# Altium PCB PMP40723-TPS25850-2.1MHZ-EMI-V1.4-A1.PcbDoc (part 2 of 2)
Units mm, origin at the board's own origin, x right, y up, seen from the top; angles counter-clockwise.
Board outline 50 x 35 mm, 4 copper layers (Top Layer, Signal Layer 1, Signal Layer 2, Bottom Layer), stack 1.647 mm thick; 79 components, 26 nets, 228 pads, 232 vias.
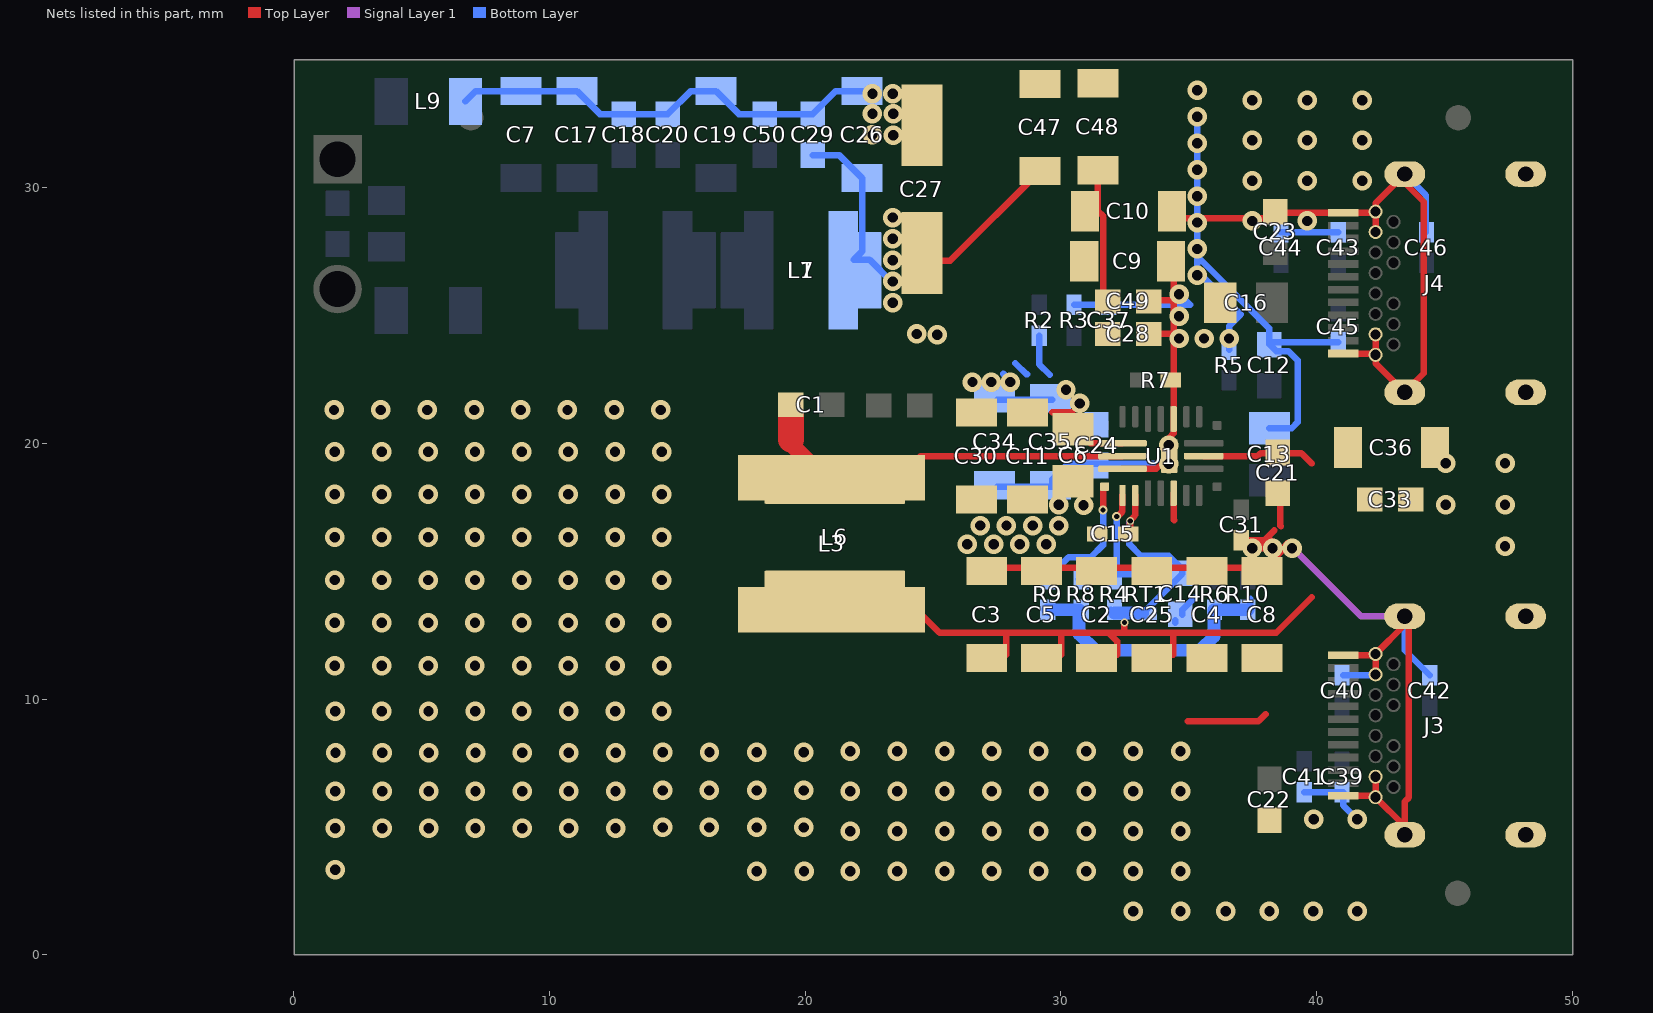
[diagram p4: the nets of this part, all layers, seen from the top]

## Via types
v1: diameter 0.762, hole 0.406, Top Layer to Bottom Layer, 201 vias
v2: diameter 0.305, hole 0.203, Top Layer to Bottom Layer, 11 vias
v3: diameter 0.356, hole 0.203, Top Layer to Bottom Layer, 8 vias
v4: diameter 0.762, hole 0.406, Top Layer to Bottom Layer, tented top, 8 vias
v5: diameter 0.356, hole 0.203, Top Layer to Bottom Layer, tented top, 2 vias
v6: diameter 0.305, hole 0.203, Top Layer to Bottom Layer, tented top, 2 vias

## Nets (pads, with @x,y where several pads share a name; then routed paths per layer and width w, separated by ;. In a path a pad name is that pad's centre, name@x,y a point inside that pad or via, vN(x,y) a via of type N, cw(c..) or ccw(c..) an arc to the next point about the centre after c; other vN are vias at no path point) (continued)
PGND: C2.2 C3.2 C4.2 C5.2 C6.2 C7.2 C8.2 C9.2 C10.2 C11.2 C12.2 C13.2 C14.2 C15.2 C16.2 C17.2 C18.2 C19.2 C20.2 C21.2 C22.2 C23.2 C24.2 C25.2 C26.2 C27.2 C28.2 C29.2 C30.2 C31.2 C33.2 C34.2 C35.2 C36.2 C37.2 C39.2 C40.2 C41.2 C42.2 C43.2 C44.2 C45.2 C46.2 C47.2 C48.2 C49.2 C50.2 J3.A1 J3.A12 J3.B1 J3.B12 J3.M1 J3.M2 J3.S1 J3.S2 J3.S3 J3.S4 J4.A1 J4.A12 J4.B1 J4.B12 J4.M1 J4.M2 J4.S1 J4.S2 J4.S3 J4.S4 L9.2 R3.1 R5.1 R6.1 R7.1 R8.1 R9.1 R10.1 U1.6 U1.16 U1.24 U1.25 | length 155.2
  Top Layer w0.254: C3.2@27.783,15.137 30.078,15.137 ; 30.072,15.143 30.078,15.137 ; C6.2@30.881,18.146 C6.2@31.124,18.39 ; U1.24@32.404,19.007 33.729,19.007 U1.25@34.229,19.507 ; C28.2@33.434,24.283 34.328,24.283 v1@34.404,24.206 ; C49.2@33.434,25.603 34.303,25.603 34.404,25.502 ; v1@34.236,20.227 34.404,20.395 U1.16@34.404,20.957 34.411,20.964 34.411,22.548 34.407,22.544 34.407,22.393 R7.1@34.404,22.39 ; C9.2@34.244,27.567 34.204,27.567 C9.2@34.259,27.621 ; R7.1@34.361,22.347 R7.1@34.404,22.39 ; U1.6@34.404,18.057 34.404,17.025 34.437,16.993 ; C10.2@34.619,28.817 38.004,28.817 38.204,29.017 J4.A12@41.044,29.017 42.254,29.017 J4.B1@42.304,29.067 ; C9.2@34.716,27.432 34.404,27.12 34.404,25.502 ; 34.963,9.133 37.72,9.133 38.004,9.417 ; C31.2@37.054,16.215 37.956,16.215 ; v1(37.486,15.901) v1@37.641,15.901 ; 38.349,16.609 37.956,16.215 ; C21.2@38.578,18.098 38.578,16.79 38.604,16.764 ; J3.A1@41.044,6.217 42.254,6.217 J3.B12@42.304,6.167 ; J3.A12@41.044,11.717 42.254,11.717 J3.B1@42.304,11.767 ; J4.A1@41.044,23.517 J4.B12@42.254,23.517 ; J3.M2@42.304,6.967 J3.B12@42.304,6.167 ; J3.M1@42.304,10.967 J3.B1@42.304,11.767 ; J4.M2@42.304,24.267 42.304,23.567 J4.B12@42.254,23.517 ; J4.M1@42.304,28.267 J4.B1@42.304,29.067 ; J3.S1@43.444,4.697 J3.S1@43.444,5.027 ; 30.078,15.137 37.977,15.137 38.909,16.068 38.873,16.104 38.67,15.901 v1(38.273,15.901) 37.888,15.901 ; R7.1@34.404,22.39 34.404,23.622 v1@34.404,24.206 ; v1@34.404,24.206 34.404,25.502 ; v1@37.641,15.901 37.888,15.901 ; v1@37.641,15.901 37.956,16.215 ; 37.888,15.901 38.203,16.215 37.956,16.215 ; J4.B12@42.254,23.517 J4.B12@42.304,23.467 42.304,23.137 J4.S1@43.444,21.997 44.19,22.743 44.19,29.449 43.444,30.195 J4.S4@43.444,30.537 42.304,29.397 J4.B1@42.304,29.067 ; J3.B12@42.304,6.167 J3.S1@43.444,5.027 ; J3.B1@42.304,11.767 43.444,12.907 J3.S4@43.444,13.237 43.606,13.075 43.606,6.155 43.444,5.993 J3.S1@43.444,5.027
  Signal Layer 1 w0.254: v1@38.928,16.05 41.742,13.237 J3.S4@43.444,13.237
  Bottom Layer w0.254: L9.2@6.706,33.376 7.11,33.78 C7.2@8.885,33.78 C17.2@11.07,33.78 11.97,32.88 C18.2@12.898,32.88 C20.2@14.626,32.88 15.526,33.78 C19.2@16.505,33.78 17.405,32.88 C50.2@18.41,32.88 C29.2@20.29,32.88 21.19,33.78 C26.2@22.22,33.78 ; C34.2@27.503,18.315 29.662,18.315 29.662,18.593 30.285,19.215 34.196,19.215 v1(34.209,19.203) ; R3.1@30.51,25.416 C37.2@31.866,25.416 35.051,25.416 34.635,25.832 v1(34.615,25.832) ; C14.2@34.463,12.992 C14.2@34.463,13.092 ; C14.2@34.742,13.297 34.742,13.488 35.225,13.97 ; v1@35.327,32.995 35.327,28.564 v1@35.327,27.317 ; R5.1@36.571,23.663 v1(36.571,24.105) 36.571,24.587 37.028,25.045 35.327,26.746 v1@35.327,27.317 ; R10.1@37.409,13.497 37.409,13.919 ; C13.2@38.147,20.6 39.023,20.6 39.252,20.828 39.252,23.253 38.892,23.612 38.422,23.612 C12.2@38.146,23.889 ; C44.2@38.603,28.261 39.645,28.261 ; C41.2@39.518,6.367 41.042,6.367 41.042,5.842 v1(41.584,5.3) ; v4(39.626,28.702) 39.626,28.28 39.645,28.261 ; C45.2@40.838,23.962 38.219,23.962 C12.2@38.146,23.889 ; C43.2@40.838,28.261 39.645,28.261 ; C40.2@41.042,10.938 42.276,10.938 J3.M1@42.304,10.967 ; J3.S4@43.444,13.237 43.444,11.914 C42.2@44.42,10.938 ; J4.S4@43.444,30.537 44.267,29.713 C46.2@44.267,28.261 ; v1@35.327,27.317 38.146,24.498 C12.2@38.146,23.889
  Bottom Layer w0.508: R9.1@29.485,13.497 30.704,13.497 30.704,12.548 31.339,11.913 35.45,11.913 35.987,12.449 35.987,13.48 R6.1@36.004,13.497 R10.1@37.308,13.497
  other v1: 32.828,1.707 34.674,1.702 36.439,1.702 38.154,1.702 39.869,1.702 41.584,1.702 18.105,3.277 19.951,3.277 21.754,3.267 23.6,3.267 25.446,3.267 27.291,3.267 29.137,3.267 30.983,3.267 32.828,3.267 34.674,3.267 1.624,3.328 21.754,4.831 23.6,4.831 25.446,4.831 27.291,4.831 29.137,4.831 30.983,4.831 32.828,4.831 34.674,4.831 1.624,4.953 3.45,4.953 5.275,4.953 7.101,4.953 8.926,4.953 10.752,4.953 12.578,4.953 14.424,4.982 16.25,4.982 18.096,4.982 19.941,4.982 39.883,5.3 1.624,6.401 3.45,6.401 5.275,6.401 7.101,6.401 8.926,6.401 10.752,6.401 12.578,6.401 21.754,6.396 23.6,6.396 25.446,6.396 27.291,6.396 29.137,6.396 30.983,6.396 32.828,6.396 34.674,6.396 14.424,6.429 16.25,6.429 18.096,6.429 19.941,6.429 1.627,7.9 3.453,7.9 5.278,7.9 7.104,7.9 8.93,7.9 10.755,7.9 12.581,7.9 14.428,7.928 16.253,7.928 18.099,7.928 19.945,7.928 21.754,7.961 23.6,7.961 25.446,7.961 27.291,7.961 29.137,7.961 30.983,7.961 32.828,7.961 34.674,7.961 1.612,9.525 3.438,9.525 5.264,9.525 7.089,9.525 8.915,9.525 10.741,9.525 12.566,9.525 14.392,9.525 1.605,11.31 3.43,11.31 5.256,11.31 7.082,11.31 8.907,11.31 10.733,11.31 12.558,11.31 14.384,11.31 1.605,12.985 3.43,12.985 5.256,12.985 7.082,12.985 8.907,12.985 10.733,12.985 12.558,12.985 14.384,12.985 1.605,14.659 3.43,14.659 5.256,14.659 7.082,14.659 8.907,14.659 10.733,14.659 12.558,14.659 14.384,14.659 39.035,15.901 47.366,15.985 26.335,16.053 27.364,16.053 28.392,16.053 29.421,16.053 1.605,16.334 3.43,16.334 5.256,16.334 7.082,16.334 8.907,16.334 10.733,16.334 12.558,16.334 14.384,16.334 26.843,16.79 27.867,16.79 28.892,16.79 29.916,16.79 30.882,17.577 29.916,17.602 45.042,17.602 47.366,17.602 1.605,18.009 3.43,18.009 5.256,18.009 7.082,18.009 8.907,18.009 10.733,18.009 12.558,18.009 14.384,18.009 45.042,19.22 47.366,19.22 1.605,19.683 3.43,19.683 5.256,19.683 7.082,19.683 8.907,19.683 10.733,19.683 12.558,19.683 14.384,19.683 34.209,19.939 1.57,21.311 3.396,21.311 5.221,21.311 7.047,21.311 8.872,21.311 10.698,21.311 12.524,21.311 14.349,21.311 34.615,24.105 35.593,24.105 25.167,24.257 24.354,24.283 34.615,24.968 35.327,26.572 35.327,27.606 35.327,28.639 35.327,29.673 41.778,30.277 35.327,30.707 35.327,31.74 41.778,31.852 23.439,32.055 22.627,32.08 35.327,32.774 22.627,32.893 23.439,32.893 41.778,33.427 22.627,33.681 23.414,33.681 35.327,33.808
  other v4: 37.473,28.702 37.473,30.277 39.626,30.277 37.473,31.852 39.626,31.852 37.473,33.427 39.626,33.427
SENS: C2.1 C3.1 C4.1 C5.1 C8.1 C14.1 C15.1 C21.1 C25.1 C33.1 C36.1 L3.2 L6.2 R4.2 RT1.2 U1.3 U1.11 | length 35
  Top Layer w0.254: L3.2@23.846,14.006 25.252,12.6 27.834,12.6 ; C3.1@27.859,11.737 27.859,12.575 27.834,12.6 ; C5.1@30.003,11.737 30.003,12.531 30.072,12.6 ; 32.198,11.737 32.198,12.255 31.857,12.596 ; v2(32.482,12.996) 32.482,12.6 ; C15.1@32.625,16.459 C15.1@32.685,16.52 ; v2@32.685,16.967 C15.1@32.685,16.52 ; v2@32.696,16.982 32.861,17.148 32.861,17.16 32.904,17.202 U1.3@32.904,17.97 ; v2(32.71,16.967) 32.71,16.545 C15.1@32.685,16.52 ; 34.393,11.737 34.393,12.583 34.411,12.6 ; U1.11@35.579,19.507 37.695,19.507 37.804,19.617 39.404,19.617 39.804,19.216 ; 39.804,13.986 38.419,12.6 34.411,12.6 ; 27.834,12.6 30.072,12.6 ; 30.072,12.6 31.567,12.6 31.572,12.596 31.857,12.596 ; 31.857,12.596 32.198,12.596 32.202,12.6 32.482,12.6 ; 32.482,12.6 34.411,12.6
  Bottom Layer w0.254: R4.2@31.948,13.497 R4.2@32.085,13.361 ; v2(32.482,12.996) 32.482,13.361 ; v2@32.668,16.918 32.668,16.064 33.121,15.611 34.218,15.611 34.742,15.086 34.742,14.897 33.312,13.466 RT1.2@33.312,13.335 ; v2@32.71,16.918 v2(32.71,16.967)
  Bottom Layer w0.508: R4.2@32.085,13.361 32.482,13.361 RT1.2@33.193,13.361
SW: C1.1 L3.1 L6.1 U1.23 | length 13.6
  Top Layer w0.254: L3.1@20.828,19.344 L3.1@21.636,19.344 ; L3.1@24.176,19.166 24.517,19.507 U1.23@32.404,19.507
  Top Layer w0.5: L3.1@22.13,19.217 L3.1@22.692,19.217
  Top Layer w0.635: 19.439,20.155 19.35,20.066 20.55,18.866 L3.1@21.611,18.866
  Top Layer w1.016: 19.439,20.155 C1.1@19.439,21.162
TS: R4.1 R8.2 RT1.1 U1.2 | length 5.8
  Top Layer w0.254: v3(32.177,17.145) 32.212,17.145 32.228,17.161 32.228,17.167 32.404,17.344 U1.2@32.404,17.97
  Bottom Layer w0.254: R8.2@30.704,14.697 31.948,14.697 R4.1@32.136,14.885 ; v3(32.177,17.145) 32.177,14.925 R4.1@32.136,14.885 ; RT1.1@33.193,14.885 R4.1@32.136,14.885
VIN: C6.1 C9.1 C10.1 C11.1 C24.1 C26.1 C27.1 C28.1 C29.1 C30.1 C34.1 C35.1 C47.1 C48.1 C49.1 L1.2 L7.2 R2.2 U1.22 | length 27.3
  Top Layer w0.254: v1@23.389,27.151 25.671,27.151 C47.1@29.18,30.66 ; 29.654,21.217 30.441,21.217 ; C6.1@30.856,20.307 31.156,20.007 U1.22@32.404,20.007 ; C48.1@31.44,30.685 31.44,29.106 31.644,28.903 31.644,25.794 C49.1@31.834,25.603
  Bottom Layer w0.254: C29.1@20.29,31.28 21.32,31.28 C26.1@22.22,30.38 22.22,27.508 21.903,27.191 22.507,27.191 v1@23.389,26.309 ; C34.1@27.503,21.715 C35.1@29.662,21.715 ; 27.732,22.733 28.011,22.454 v1@28.011,22.428 ; 28.215,23.14 28.646,22.708 28.672,22.708 ; R2.2@29.154,24.216 29.154,23.089 29.561,22.682
  other v1: 30.729,21.565 30.196,22.098 26.538,22.403 27.275,22.403 28.011,22.403 23.414,25.502 23.414,26.335 23.414,27.169 23.414,28.002 23.414,28.835
VSET: R9.2 U1.1 | length 5
  Top Layer w0.254: v3(31.644,17.399) 31.644,18.247 U1.1@31.704,18.307
  Bottom Layer w0.254: R9.2@29.485,14.697 29.485,14.732 30.297,15.545 31.161,15.545 31.644,16.028 v3(31.644,17.399)
pads on no net: FID1.1 FID2.1 FID3.1 J3.A2 J3.A3 J3.A8 J3.A10 J3.A11 J3.B2 J3.B3 J3.B8 J3.B10 J3.B11 J4.A2 J4.A3 J4.A8 J4.A10 J4.A11 J4.B2 J4.B3 J4.B8 J4.B10 J4.B11

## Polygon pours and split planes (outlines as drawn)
VIN on Top Layer "TOP_LAYER_VIN_P134" (solid, remove dead copper, pour order 134): 22.855,29.312 24.938,29.312 27.3,31.674 32.2,31.674 32.456,31.418 32.456,30.277 32.456,26.137 32.456,23.47 31.898,22.911 30.805,22.911 30.551,22.657 30.551,22.352 31.288,21.616 31.288,20.139 31.156,20.007 31.072,20.092 30.043,20.092 29.51,20.625 25.903,20.625 25.779,20.749 25.779,22.965 25.929,23.114 28.144,23.114 30.183,25.153 30.183,26.387 30.183,29.401 29.815,29.769 28.392,29.769 25.573,26.95 25.573,25.248 25.319,24.994 22.787,24.994 22.41,25.371 22.41,28.965
SW on Top Layer "TOP_LAYER_SW_P120" (solid, remove dead copper, pour order 120): 17.19,20.015 17.496,20.32 18.602,20.32 18.932,20.65 19.835,20.65 20.166,20.32 29.383,20.32 29.535,20.168 29.535,19.736 29.612,19.66 29.612,19.406 29.535,19.33 29.535,18.695 29.442,18.602 25.688,18.602 25.586,18.499 25.586,17.702 25.384,17.501 17.336,17.501 17.19,17.647
no net on Top Layer "TOP_LAYER_NONET_P114" (solid, remove dead copper, pour order 114): 17.928,20.32
PGND on Top Layer "TOP_LAYER_PGND_P096" (solid, remove dead copper, pour order 96): 22.627,34.57 48.382,34.57 49.424,33.528 49.424,1.651 48.408,0.635 0.851,0.635 0.554,0.933 0.554,22.759 1.799,24.003 21.23,24.003 22.211,24.984 22.234,34.177
PB_BUS on Top Layer "TOP_LAYER_PB_BUS_P090" (solid, remove dead copper, pour order 90): 36.451,20.87 36.536,20.955 36.609,20.955 37.587,21.932 37.587,27.858 37.77,28.042 40.026,28.042 40.441,27.626 40.441,27.365 40.178,27.102 39.314,27.102 39.137,26.924 39.137,25.908 39.924,25.121 40.356,25.121 40.441,25.035 40.441,24.892 40.407,24.892 39.846,24.331 39.846,21.258 39.543,20.955 37.662,20.955 36.68,20.168 36.494,20.168 36.451,20.2
no net on Top Layer "TOP_LAYER_NONET_P088" (solid, remove dead copper, pour order 88): 36.104,20.523
SENS on Top Layer "TOP_LAYER_SENS_P086" (solid, remove dead copper, pour order 86): 36.399,19.513 37.689,20.803 42.159,20.803 42.896,20.066 42.896,14.443 38.755,10.236 17.597,10.236 17.19,10.644 17.19,15.161 17.625,15.596 25.376,15.596 25.573,15.399 25.573,13.44 25.779,13.234 38.786,13.234 40.711,15.159 40.711,18.568 40.234,19.045 37.669,19.045 37.384,19.33 36.583,19.33
no net on Top Layer "TOP_LAYER_NONET_P050" (solid, remove dead copper, pour order 50): 22.652,33.808
PA_BUS on Top Layer "TOP_LAYER_PA_BUS_P012" (solid, remove dead copper, pour order 12): 35.606,7.826 35.908,8.128 38.519,8.128 38.713,8.321 38.713,9.671 39.491,10.45 40.355,10.45 40.558,10.247 40.558,10.167 40.279,9.891 40.279,9.637 40.202,9.561 39.517,9.561 39.263,9.307 39.263,8.062 39.466,7.859 40.431,7.859 40.533,7.758 40.507,7.732 40.507,7.605 40.267,7.365 40.267,6.64 39.962,6.335 35.697,6.335 35.606,6.426
PA_BUS on Top Layer "TOP_LAYER_PA_BUS_P006" (solid, remove dead copper, pour order 6): 36.292,19.076 36.343,19.126 37.303,19.126 37.486,18.943 37.486,17.069 37.308,16.891 36.8,16.891 36.648,17.043 36.648,18.64 36.314,18.974 36.241,18.974
VIN on Signal Layer 1 "SIGNAL_LAYER_1_VIN_P098" (solid, remove dead copper, pour order 98): 26.157,22.733 26.53,23.106 29.705,23.106 29.761,23.114 31.216,21.66 31.207,21.052 30.788,20.633 27.698,20.633 26.157,22.174
PGND on Signal Layer 1 "SIGNAL_LAYER_1_PGND_P080" (solid, remove dead copper, pour order 80): 24.836,34.646 48.865,34.646 49.576,33.935 49.576,1.524 48.763,0.711 0.986,0.711 0.656,1.042 0.656,21.895 1.087,22.327 23.363,22.327 24.009,22.972 24.036,33.846
PA_BUS on Signal Layer 1 "SIGNAL_LAYER_1_PA_BUS_P044" (solid, remove dead copper, pour order 44): 36.725,19.164 37.36,19.164 37.487,19.037 37.487,17.005 37.36,16.878 36.725,16.878 36.598,17.005 36.598,19.037
PGND on Signal Layer 2 "SIGNAL_LAYER_2_PGND_P112" (solid, remove dead copper, pour order 112): 24.278,34.57 48.665,34.57 49.554,33.681 49.554,1.27 48.919,0.635 1.007,0.635 0.634,1.009 0.634,21.873 1.062,22.301 23.312,22.301 23.985,22.974 24.014,34.306
PA_BUS on Signal Layer 2 "SIGNAL_LAYER_2_PA_BUS_P106" (solid, remove dead copper, pour order 106): 36.899,19.203 42.388,19.203 46.528,15.062 46.528,3.658 45.207,2.337 36.978,2.337 35.509,3.806 35.509,7.932 35.806,8.23 37.305,8.23 37.562,7.973 37.562,4.445 38.07,3.937 44.267,3.937 44.648,4.318 44.648,14.148 41.905,16.891 36.8,16.891 36.597,17.094 36.597,18.9
VIN on Signal Layer 2 "SIGNAL_LAYER_2_VIN_P072" (solid, remove dead copper, pour order 72): 26.081,22.664 26.733,23.316 30.231,23.316 30.983,22.564 30.983,21.892 31.263,21.613 31.263,20.788 31.201,20.727 26.273,20.727 26.081,20.836
PGND on Bottom Layer "BOTTOM_LAYER_PGND_P132" (solid, remove dead copper, pour order 132): 5.983,34.366 12.086,34.366 12.67,33.782 12.67,33.757 14.778,33.757 15.464,34.443 17.674,34.443 18.359,33.757 20.493,33.757 21.103,34.366 23.82,34.366 23.973,34.214 23.973,31.776 23.77,31.572 22.449,31.572 21.788,32.233 17.953,32.233 17.191,32.995 15.959,32.995 15.298,32.334 12.314,32.334 11.578,33.071 7.895,33.071 7.539,32.715 7.539,32.334 7.437,32.233 6.04,32.233 5.863,32.411 5.863,34.27
VIN on Bottom Layer "BOTTOM_LAYER_VIN_P130" (solid, remove dead copper, pour order 130): 19.756,31.852 21.204,31.852 21.839,31.217 23.058,31.217 23.82,30.455 23.82,24.689 23.541,24.41 20.96,24.41 20.772,24.597 20.772,30.125 20.366,30.531 19.629,30.531 19.502,30.658 19.502,31.623
NetC19_1 on Bottom Layer "BOTTOM_LAYER_NETC19_1_P128" (solid, remove dead copper, pour order 128): 14.041,31.699 14.194,31.852 18.893,31.852 19.045,31.699 19.045,24.384 18.817,24.156 14.254,24.156 14.041,24.368
NetC7_1 on Bottom Layer "BOTTOM_LAYER_NETC7_1_P126" (solid, remove dead copper, pour order 126): 5.913,26.162 6.117,26.365 6.498,26.365 6.828,26.696 6.828,30.302 7.564,31.039 11.425,31.039 12.238,31.852 13.508,31.852 13.737,31.623 13.737,30.937 12.492,29.693 12.492,24.384 12.213,24.105 10.282,24.105 10.054,24.333 10.054,29.388 9.85,29.591 8.479,29.591 8.199,29.312 8.199,24.054 8.072,23.927 6.075,23.927 5.939,24.064
+BAT on Bottom Layer "BOTTOM_LAYER_+BAT_P124" (solid, remove dead copper, pour order 124): 0.922,28.499 4.491,28.499 4.72,28.27 4.72,24.181 4.364,23.825 0.96,23.825 0.452,24.333 0.452,28.029
NetC32_2 on Bottom Layer "BOTTOM_LAYER_NETC32_2_P122" (solid, remove dead copper, pour order 122): 1.214,34.62 4.212,34.62 4.745,34.087 4.745,29.286 4.339,28.88 1.02,28.88 0.478,29.422 0.478,33.884
PA_BUS on Bottom Layer "BOTTOM_LAYER_PA_BUS_P108" (solid, remove dead copper, pour order 108): 36.851,19.38 39.052,19.38 39.264,19.169 39.264,17.12 39.061,16.918 36.773,16.918 36.597,17.094 36.597,19.126
VIN on Bottom Layer "BOTTOM_LAYER_VIN_P056" (solid, remove dead copper, pour order 56): 26.571,23.42 29.894,23.42 31.597,21.717 32.092,21.221 32.092,20.302 31.984,20.193 26.369,20.193 26.106,20.456 26.106,23.055
PGND on Bottom Layer "BOTTOM_LAYER_PGND_P058" (solid, remove dead copper, pour order 58): 24.455,34.062 24.963,34.57 48.806,34.57 49.416,33.96 49.416,1.423 48.654,0.661 1.308,0.661 0.572,1.397 0.572,21.85 0.973,22.251 21.839,22.251 24.455,24.867

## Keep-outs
Keep-Out Layer:
  text ".Layer_Name" at -27.792,-42.075 h1.52

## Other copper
Top Layer:
  pour cut-out: 22.995,24.787 21.996,24.787 21.839,24.943 21.839,29.642 21.865,29.667 22.22,29.667 22.373,29.515 23.015,29.515 23.017,29.514 22.978,29.475 22.705,29.475 22.347,29.117 22.41,29.054 22.41,25.371 22.728,25.053 22.728,24.994
  pour cut-out: 25.339,24.791 25.446,24.684 25.446,24.638 25.551,24.638 25.576,24.663 25.576,23.012 25.793,23.23 25.793,24.714
  pour cut-out: 23.033,29.613
  pour cut-out: 25.624,17.572 25.446,17.394 25.446,15.687 25.624,15.509
  pour cut-out: 32.279,22.136 32.427,22.284 32.427,22.196 32.431,22.192 32.431,22.149
  pour cut-out: 17.023,17.774 17.023,15.377 17.369,15.814 17.369,15.959 17.369,17.468 17.063,17.774
  pour cut-out: 33.472,19.236 33.472,20.236 33.545,20.309 33.545,19.309
  pour cut-out: 43.466,28.689 43.466,23.889 43.425,23.889 43.352,23.963 43.352,28.509
  pour cut-out: 43.492,11.367 43.492,6.567 43.451,6.567 43.377,6.64 43.377,11.187
  pour cut-out: 34.596,19.867 34.591,19.872 34.591,21.018 34.669,20.939 34.669,19.94
  pour cut-out: 32.113,18.741 33.793,18.741 33.844,18.69 32.136,18.69
  text ".Layer_Name" at -27.792,-42.075 h1.52
Signal Layer 1:
  pour cut-out: 23.363,22.327 25.798,22.327 25.95,22.174 25.966,22.19 25.966,22.812 24.169,22.812 24.009,22.972
  pour cut-out: 43.439,26.782 43.439,25.548 43.428,25.538 43.191,25.775 43.191,25.917
  pour cut-out: 43.349,9.422 43.455,9.316 43.455,8.353 43.349,8.459
Signal Layer 2:
  pour cut-out: 42.402,22.49 42.427,22.466 42.427,19.402 42.375,19.402 42.367,19.41 42.058,19.41 42.058,22.479 42.032,22.505
  pour cut-out: 23.312,22.301 25.256,22.301 25.497,22.061 25.624,22.061 25.624,21.793 25.678,21.848 25.852,21.848 25.852,22.759 26.274,23.181 24.211,23.181 24.024,23.368 23.846,23.368 23.846,23.282 23.744,23.181
  pour cut-out: 43.455,8.353 43.481,8.38 43.481,9.43 43.357,9.43 43.349,9.422 43.349,8.511
Bottom Layer:
  pour cut-out: 30.404,24.754 32.179,24.754 32.179,24.834 30.404,24.834
  pour cut-out: 21.839,22.251 21.865,22.276 25.903,22.276 25.903,22.26 25.988,22.175 25.988,23.126 26.481,23.619 24.306,23.619 23.772,24.153
  pour cut-out: 37.145,22.831 37.442,22.831 37.442,22.832 37.442,22.911 37.145,22.911
  pour cut-out: 34.272,16.929 34.569,16.929 34.569,16.93 34.569,17.009 34.272,17.009
  pour cut-out: 39.8,25.68 39.8,26.353 39.72,26.353 39.72,25.68
  pour cut-out: 41.287,24.714 41.959,24.714 41.959,24.794 41.287,24.794
  pour cut-out: 39.099,27.584 41.854,27.584 41.854,27.664 39.099,27.664
  pour cut-out: 41.528,10.207 41.826,10.207 41.825,10.208 41.825,10.287 41.528,10.287
  pour cut-out: 41.579,7.287 41.876,7.287 41.876,7.367 41.579,7.367
  pour cut-out: 40.004,6.956 40.302,6.956 40.301,6.957 40.301,7.036 40.004,7.036
  pour cut-out: 36.524,14.094 36.822,14.094 36.821,14.094 36.821,14.173 36.524,14.173
  pour cut-out: 31.292,14.094 31.589,14.094 31.589,14.173 31.292,14.173
  pour cut-out: 29.988,14.094 30.285,14.094 30.285,14.173 29.988,14.173
  pour cut-out: 5.253,24.689
  pour cut-out: 43.456,26.751 43.456,25.88 43.415,25.839 43.098,25.839 43.098,26.562 43.2,26.664
  pour cut-out: 43.405,9.432 43.405,8.561 43.364,8.52 43.047,8.52 43.047,9.243 43.149,9.344
  pour cut-out: 33.464,13.95
  text ".Layer_Name" at -27.792,-42.075 h1.52

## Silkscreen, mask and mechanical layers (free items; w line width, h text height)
Top Overlay:
  lines w0.01: 15.24,23.266 15.245,23.271 ; 39.535,8.992 39.54,8.996 ; 39.535,22.123 39.54,22.128
  lines w0.1: 39.535,8.992 15.24,8.992 15.24,23.271 39.54,23.271 39.54,8.996
  lines w0.254: 30.646,17.038 ccw(c30.475,16.967) 30.66,16.967
  text "GND" at 4.491,30.379 h1.27
  text "VIN" at 4.491,25.451 h1.27
  text "PMP40723" at 3.272,2.362 h3.05
  text ".Layer_Name" at -27.792,-42.075 h1.52
Bottom Overlay:
  text "GND" at 0.275,33.985 h1.27 r180
  text "VIN" at 0.732,24.892 h1.27 r180
  text ".Layer_Name" at -27.792,-42.075 h1.52
Top Paste:
  text ".Layer_Name" at -27.792,-42.075 h1.52
Bottom Paste:
  text ".Layer_Name" at -27.792,-42.075 h1.52
Top Solder:
  circle w0.508: c39.364,7.074 r0.238
  circle w0.508: c2.764,31.369 r0.238
  circle w0.508: c38.374,25.667 r0.238
  region: 15.791,11.024 14.648,11.024 14.648,8.687 15.791,8.687
  region: 16.959,8.407 16.959,9.55 14.623,9.55 14.623,8.407
  region: 17.318,22.657 17.318,23.8 14.981,23.8 14.981,22.657
  region: 24.917,8.407 24.917,9.55 22.581,9.55 22.581,8.407
  region: 37.363,22.657 37.363,23.8 35.027,23.8 35.027,22.657
  rectangle: 38.989,14.935 40.132,17.272
  region: 35.027,9.55 35.027,8.407 37.363,8.407 37.363,9.55
  region: 15.799,17.272 14.656,17.272 14.656,14.935 15.799,14.935
  region: 24.917,22.657 24.917,23.8 22.581,23.8 22.581,22.657
  rectangle: 14.648,21.457 15.791,23.794
  rectangle: 30.83,20.6 31.136,21.133
  region: 3.221,29.921 3.221,32.157 0.122,32.157 0.122,29.921
  region: 3.297,24.943 3.297,27.178 0.198,27.178 0.198,24.943
  rectangle: 31.085,19.355 31.661,19.685
  rectangle: 31.085,18.847 31.661,19.177
  rectangle: 31.085,19.863 31.66,20.193
  rectangle: 36.288,18.847 36.795,19.177
  rectangle: 36.288,19.355 36.795,19.685
  rectangle: 36.141,19.838 36.647,20.168
  region: 36.292,20.61
  region: 36.292,20.519
  region: 26.563,18.661
  lines w0.01: 14.854,9.271 17.648,9.271 ; 15.54,8.662 15.54,11.303
  text ".Layer_Name" at -27.792,-42.075 h1.52
  text ".Layer_Name" at -27.792,-42.075 h1.52
Bottom Solder:
  circle w0.254: c38.527,17.587 r0.127
  circle w0.254: c37.282,16.142 r0.127
  rectangle: 23.109,31.649 23.922,33.909
  rectangle: 24.557,31.674 25.852,33.935
  rectangle: 33.114,18.085 35.35,21.031
  region: 3.754,30.277 3.754,32.106 3.018,32.106 3.018,30.277
  text ".Layer_Name" at -27.792,-42.075 h1.52
Drill Guide:
  text ".Layer_Name" at -27.792,-42.075 h1.52
M1 Board Outline:
  lines w0.01: 0.512,34.25 0.521,34.25 ; 0.021,0 0.021,35 50.021,35 50.021,0 0.021,0 ; 0.021,50 0.021,50
  text ".Layer_Name" at -27.792,-42.075 h1.52
M2 Board Dimensions:
  rectangle: -42.448,-27.254 -39.273,-24.079
  rectangle: -39.273,-30.429 -29.748,-27.254
  lines w0.178: -42.448,-27.254 -17.048,-27.254 ; -42.448,-24.079 -42.448,-30.429 -17.048,-30.429 -17.048,-24.079 ; -39.273,-30.429 -39.273,-24.079 ; -36.098,-30.429 -36.098,-24.079 ; -29.748,-30.429 -29.748,-24.079 ; -23.398,-30.429 -23.398,-24.079
  text ".Layer_Name" at -27.792,-42.075 h1.52
M3 3D STEP Top:
  text ".Layer_Name" at -27.792,-42.075 h1.52
M4 3D STEP Bottom:
  text ".Layer_Name" at -27.792,-42.075 h1.52
M5 Assembly Top:
  lines w0.254: -49.865,-43.895 117.775,-43.895 ; -49.865,-38.731 117.826,-38.731 ; -49.865,-33.566 -49.865,-49.06 51.862,-49.06 117.826,-49.06 117.826,-33.566 -49.852,-33.566 -49.852,-49.06 -9.835,-49.06 ; 12.746,-49.06 12.746,-33.566 ; 44.928,-38.731 44.928,-33.566 ; 66.264,-38.731 66.264,-33.566 ; 82.063,-49.225 82.063,-44.073
  text "COMPONENTS MARKED 'DNP' SHOULD NOT BE POPULATED." at -13.149,-28.359 h1.52
  text "ASSEMBLY VARIANT:" at -13.162,-31.293 h1.52
  text ".VariantName" at 13.152,-31.293 h1.52
  text "PCB VIEWED FROM TOP SIDE" at -48.252,-36.923 h1.52
  text "BOARD #:" at 14.651,-36.923 h1.52
  text ".PRJ_Number" at 28.507,-36.923 h1.52
  text "REV:" at 49.957,-36.923 h1.52
  text ".PCB_Rev" at 57.361,-36.923 h1.52
  text "SVN REV:" at 71.242,-36.923 h1.52
  text ".VersionControl_RevNumber" at 84.095,-36.923 h1.52
  text "TID #:" at 14.651,-42.088 h1.52
  text ".TID" at 28.507,-42.088 h1.52
  text "PLOT NAME =" at -48.252,-47.303 h1.52
  text ".plot_File_Name" at -27.792,-47.303 h1.52
  text "GENERATED    :" at 14.702,-47.303 h1.52
  text ".Print_Date" at 36.787,-47.303 h1.52
  text ".Print_Time" at 55.304,-47.303 h1.52
  text "TEXAS INSTRUMENTS" at 87.422,-47.303 h1.52
M6 Assembly Bottom:
  lines w0.254: -49.878,-38.743 117.813,-38.743 ; -49.827,-43.908 117.813,-43.908 ; -14.115,-49.238 -14.115,-44.086 ; 1.684,-38.743 1.684,-33.579 ; 23.02,-38.743 23.02,-33.579 ; 55.202,-49.073 55.202,-33.579 ; 77.783,-49.073 117.8,-49.073 117.8,-33.579 -49.878,-33.579 -49.878,-49.073 16.086,-49.073 117.813,-49.073 117.813,-33.579
  text "COMPONENTS MARKED 'DNP' SHOULD NOT BE POPULATED." at 112.543,-28.346 h1.52
  text ".VariantName" at 86.025,-31.293 h1.52
  text "ASSEMBLY VARIANT:" at 112.416,-31.293 h1.52
  text ".VersionControl_RevNumber" at -16.147,-36.936 h1.52
  text "SVN REV:" at -3.294,-36.936 h1.52
  text ".PCB_Rev" at 10.587,-36.936 h1.52
  text "REV:" at 17.991,-36.936 h1.52
  text ".PRJ_Number" at 39.441,-36.936 h1.52
  text "BOARD #:" at 53.297,-36.936 h1.52
  text "PCB VIEWED FROM BOTTOM SIDE" at 116.2,-36.936 h1.52
  text ".TID" at 39.441,-42.1 h1.52
  text "TID #:" at 53.297,-42.1 h1.52
  text "TEXAS INSTRUMENTS" at -19.474,-47.316 h1.52
  text ".Print_Time" at 12.644,-47.316 h1.52
  text ".Print_Date" at 31.161,-47.316 h1.52
  text "GENERATED    :" at 53.246,-47.316 h1.52
  text ".plot_File_Name" at 95.74,-47.316 h1.52
  text "PLOT NAME =" at 116.2,-47.316 h1.52
M9 Title Sheet:
  drawing of 57 lines, arcs and shapes, not listed
  text "1" at -23.656,183.858 h1.78
  text "2" at 39.733,183.858 h1.78
  text "3" at 102.963,183.858 h1.78
  text "4" at 166.632,183.858 h1.78
  text "5" at 230.106,183.858 h1.78
  text "6" at 293.733,183.858 h1.78
  text "A" at -53.027,154.826 h1.78
  text "A" at 322.893,154.826 h1.78
  text "B" at -53.027,94.374 h1.78
  text "B" at 322.893,94.374 h1.78
  text "C" at -53.027,34.049 h1.78
  text "C" at 322.893,34.049 h1.78
  text "PROJECT TITLE:" at 245.677,-13.22 h1.14
  text ".PRJ_Title" at 246.947,-16.607 h1.78
  text "DESIGNED FOR:" at 245.677,-20.866 h1.14
  text ".PRJ_Customer" at 246.947,-24.422 h1.78
  text "D" at -53.027,-26.149 h1.78
  text "D" at 322.893,-26.149 h1.78
  text "FILE NAME:" at 245.677,-28.486 h1.14
  text ".PCB_File_Name_No_Path" at 246.947,-31.534 h1.78
  text "Texas Instruments (TI) and/or its licensors do not warrant the accuracy or completeness of this specification" at 119.451,-35.645 h1.14
  text "ENGINEER:" at 245.677,-35.852 h1.14
  text "LAYOUT BY:" at 283.904,-35.852 h1.14
  text "or any information contained therein. TI and/or its licensors do not warrant that this design will meet" at 118.309,-38.506 h1.14
  text ".PRJ_Engineer" at 246.947,-39.789 h1.78
  text ".PCB_Layout" at 285.186,-39.789 h1.78
  text "the specifications, will be suitable for your application or fit for any particular purpose, or will operate in" at 118.309,-41.368 h1.14
  text ".Layer_Name" at -27.792,-42.075 h1.52
  text "ALTIUM DESIGNER VERSION:" at 283.904,-43.726 h1.14
  text "an implementation. TI and/or its licensors do not warrant that the design is production worthy. You should" at 118.309,-44.23 h1.14
  text "completely validate and test your design implementation to confirm the system functionality for your application." at 119.451,-47.091 h1.14
  text ".print_Scale" at 246.947,-47.112 h1.78
  text ".Application_BuildNumber" at 285.186,-47.112 h1.78
  text "1" at -23.656,-52.362 h1.78
  text "2" at 39.733,-52.362 h1.78
  text "3" at 102.963,-52.362 h1.78
  text "4" at 166.632,-52.362 h1.78
  text "5" at 230.106,-52.362 h1.78
  text "6" at 293.733,-52.362 h1.78
M10 Fab Notes:
  drawing of 189 lines, arcs and shapes, not listed
  text "DESIGN INFORMATION" at 272.055,141.178 h1.52
  text "MIN. TRACK WIDTH:" at 255.683,137.822 h1.52
  text "8" at 283.528,137.822 h1.52
  text "MIL" at 287.459,137.822 h1.52
  text "MIN. CLEARANCE:" at 255.683,134.669 h1.52
  text "0.2" at 282.004,134.669 h1.52
  text "mm" at 287.459,134.669 h1.52
  text "MIN. VIA PAD SIZE:" at 255.683,131.516 h1.52
  text "24" at 282.766,131.516 h1.52
  text "MIL" at 287.459,131.516 h1.52
  text "0.05mm (2MIL)" at 273.336,128.217 h1.52
  text "MINIMUM ANNULAR RING" at 247.321,128.008 h1.52
  text "EXTERNAL" at 291.319,128.008 h1.52
  text "PER" at 252.401,125.211 h1.52
  text "IPC-D-275 CLASS 2 LEVEL C" at 257.989,125.211 h1.52
  text "MIL, HOLES" at 295.79,122.659 h1.52
  text "+/-" at 285.821,122.44 h1.52
  text "+/-" at 307.513,122.44 h1.52
  text "REGISTRATION TOLERANCES:" at 247.321,122.413 h1.52
  text "METAL" at 277.795,122.413 h1.52
  text "5" at 292.431,122.414 h1.52
  text "3" at 313.589,122.414 h1.52
  text "MIL" at 316.542,122.413 h1.52
  text "HOLE SIZE TOLERANCE (UNLESS OTHERWISE SPECIFIED):" at 247.321,119.916 h1.52
  text "+/-" at 307.513,119.843 h1.52
  text "3" at 313.589,119.816 h1.52
  text "MIL" at 316.542,119.816 h1.52
  text "MATERIAL:" at 245.422,116.32 h1.52
  text "FR-4 High Tg" at 270.477,113.055 h1.52
  text "X" at 266.809,112.853 h1.52
  text "FR-408" at 256.115,112.738 h1.52
  text "OTHER" at 293.91,112.738 h1.52
  text "62 MIL (1.6mm) +/-10%" at 264.246,109.105 h1.52
  text "X" at 261.195,109.043 h1.52
  text "THICKNESS:" at 247.321,108.896 h1.52
  text "OTHER" at 296.882,108.896 h1.52
  text "TOLERANCE:" at 247.321,105.383 h1.52
  text "X" at 268.866,105.383 h1.52
  text "ANSI IPC-6012 TYPE 3 CLASS 2" at 273.387,105.383 h1.52
  text "OTHER +/-" at 273.387,101.72 h1.52
  text "BOW & TWIST:" at 247.321,98.033 h1.52
  text "X" at 268.866,98.033 h1.52
  text "ANSI IPC-6012 TYPE 3 CLASS 2" at 273.387,98.033 h1.52
  text "OTHER +/-" at 273.387,94.307 h1.52
  text "DRILLING:" at 245.422,90.989 h1.52
  text "NC_DRILL FILES" at 290.151,88.317 h1.52
  text "REFERENCE:" at 247.321,88.217 h1.52
  text "X" at 264.015,88.215 h1.52
  text "AS SHOWN" at 268.536,88.217 h1.52
  text "X" at 286.9,88.217 h1.52
  text "OTHER" at 297.72,84.604 h1.52
  text "PTH COPPER THICKNESS:" at 247.313,84.514 h1.52
  text "X" at 276.249,84.514 h1.52
  text "20-30 um" at 279.5,84.514 h1.52
  text "BOARD FINISH:" at 245.422,80.765 h1.52
  text "SILKSCREEN:" at 249.364,77.968 h1.52
  text "X" at 273.692,77.968 h1.52
  text "TOP" at 276.664,77.968 h1.52
  text "X" at 286.646,77.968 h1.52
  text "BOTTOM" at 289.643,77.968 h1.52
  text "SILKSCREEN COLOR:" at 249.364,74.026 h1.52
  text "X" at 273.667,74.026 h1.52
  text "WHITE" at 276.664,74.026 h1.52
  text "OTHER" at 289.643,74.026 h1.52
  text "X" at 276.994,70.383 h1.52
  text "GREEN" at 279.991,70.383 h1.52
  text "OTHER" at 295.688,70.383 h1.52
  text "SOLDER RESIST COLOR:" at 249.364,70.208 h1.52
  text "X" at 276.994,66.465 h1.52
  text "MATTE" at 279.991,66.465 h1.52
  text "SEMI-GLOSS" at 295.677,66.448 h1.52
  text "IMMERSION GOLD (ENIG)" at 272.371,62.076 h1.52
  text "ENEPIG" at 306.345,61.893 h1.52
  text "SURFACE FINISH:" at 245.422,61.867 h1.52
  text "X" at 267.85,61.867 h1.52
  text "IMM. TIN/SILVER OR EQUIV" at 253.792,58.38 h1.52
  text "OTHER" at 290.151,58.28 h1.52
  text "ARRAY/PANEL:" at 245.422,54.333 h1.52
  text "CUT AND TRIM PER M1 BOARD OUTLINE" at 272.371,54.124 h1.52
  text "N.C. ROUTE" at 272.371,50.671 h1.52
  text "X" at 289.846,50.671 h1.52
  text "V. SCORE" at 294.367,50.671 h1.52
  text "CERTIFICATION:" at 245.422,47.391 h1.52
  text "MATERIALS AND WORKMANSHIP FOR ALL PCBS" at 263.837,47.391 h1.52
  text "TO MEET OR EXCEED THE REQUIREMENTS OF:" at 263.837,45.002 h1.52
  text "X" at 254.629,41.734 h1.52
  text "ANSI IPC-A-600F CLASS ->" at 257.88,41.734 h1.52
  text "X" at 299.74,41.734 h1.52
  text "2" at 302.534,41.734 h1.52
  text "1" at 294.533,41.696 h1.52
  text "3" at 311.525,41.696 h1.52
  text "X" at 275.254,37.983 h1.52
  text "RoHS" at 278.505,37.983 h1.52
  text "OTHER" at 294.873,37.983 h1.52
  text "PER ORDER" at 304.958,37.983 h1.52
  text "ALL BOARDS MUST MEET OR EXCEED UL94-V0 REQUIREMENTS." at 246.121,34.076 h1.52
  text "PCB MUST BEAR THE UL94V-0 UL REGISTERED MATERIAL ID NUMBER" at 246.121,31.128 h1.52
  text "ADDITIONAL REQUIREMENTS:" at 245.422,26.825 h1.52
  text "MICROSECTION:" at 247.321,24.104 h1.52
  text "YES" at 270.326,24.104 h1.52
  text "REQUIRED" at 292.208,20.438 h1.52
  text "BARE BOARD ELEC. TEST:" at 247.321,20.365 h1.52
  text "NONE" at 280.486,20.365 h1.52
  text "X" at 289.211,20.365 h1.52
  text "PER ORDER" at 307.245,20.365 h1.52
  text "XX MIL VIAS REQUIRE NON-CONDUCTIVE FILL AND PLANARIZE" at 251.592,15.159 h1.5
  text "XX MIL VIAS REQUIRE CONDUCTIVE FILL AND PLANARIZE" at 251.795,12.518 h1.52
  text "OUTER XX MIL TRACES REQUIRE 50 OHM SINGLE-ENDED IMPEDANCE" at 251.77,8.368 h1.47
  text "LAYER 2 & 3 (INNER LAYERS) XX MIL WIDE, XX MIL SPACE / TRACES REQUIRE 100 OHM DIFFERENTIAL IMPEDANCE" at 251.567,2.381 h1.52
  text ".Layer_Name" at -27.792,-42.075 h1.52
M11 Gerber Information:
  lines w0.254: -49.865,-43.895 117.775,-43.895 ; -49.865,-38.731 117.826,-38.731 ; -49.865,-33.566 -49.865,-49.06 51.862,-49.06 117.826,-49.06 117.826,-33.566 -49.852,-33.566 -49.852,-49.06 -9.835,-49.06 ; 12.746,-49.06 12.746,-33.566 ; 44.928,-38.731 44.928,-33.566 ; 66.264,-38.731 66.264,-33.566 ; 82.063,-49.225 82.063,-44.073
  text "ALL ARTWORK VIEWED FROM TOP SIDE" at -48.252,-36.923 h1.52
  text "BOARD #:" at 14.651,-36.923 h1.52
  text ".PRJ_Number" at 28.507,-36.923 h1.52
  text "REV:" at 49.957,-36.923 h1.52
  text ".PCB_Rev" at 57.361,-36.923 h1.52
  text "SVN REV:" at 71.242,-36.923 h1.52
  text ".VersionControl_RevNumber" at 84.095,-36.923 h1.52
  text "LAYER NAME =" at -48.252,-42.075 h1.52
  text "TID #:" at 14.651,-42.088 h1.52
  text ".TID" at 28.507,-42.088 h1.52
  text "PLOT NAME =" at -48.252,-47.303 h1.52
  text ".plot_File_Name" at -27.792,-47.303 h1.52
  text "GENERATED    :" at 14.702,-47.303 h1.52
  text ".Print_Date" at 36.787,-47.303 h1.52
  text ".Print_Time" at 55.304,-47.303 h1.52
  text "TEXAS INSTRUMENTS" at 87.422,-47.303 h1.52
M12 Stackup:
  drawing of 243 lines, arcs and shapes, not listed
  text "Layer" at 206.766,150.608 h1.52
  text "Name" at 217.178,150.608 h1.52
  text "Material" at 241.048,150.608 h1.52
  text "Thickness" at 262.886,150.608 h1.52
  text "Constant" at 279.391,150.608 h1.52
  text "Board Layer Stack" at 293.866,150.608 h1.52
  text "1" at 206.766,147.56 h1.52
  text "Top Overlay" at 217.178,147.56 h1.52
  text "2" at 206.766,144.512 h1.52
  text "Top Solder" at 217.178,144.512 h1.52
  text "Solder Resist" at 241.048,144.512 h1.52
  text "0.40mil" at 262.886,144.512 h1.52
  text "3.5" at 279.391,144.512 h1.52
  text "3" at 206.766,141.464 h1.52
  text "Top Layer" at 217.178,141.464 h1.52
  text "Copper" at 241.048,141.464 h1.52
  text "1.40mil" at 262.886,141.464 h1.52
  text "4" at 206.766,138.416 h1.52
  text "Signal Layer 1" at 217.178,138.416 h1.52
  text "Copper" at 241.048,138.416 h1.52
  text "1.42mil" at 262.886,138.416 h1.52
  text "5" at 206.766,135.368 h1.52
  text "Signal Layer 2" at 217.178,135.368 h1.52
  text "Copper" at 241.048,135.368 h1.52
  text "1.42mil" at 262.886,135.368 h1.52
  text "6" at 206.766,132.32 h1.52
  text "Dielectric1" at 217.178,132.32 h1.52
  text "FR-4" at 241.048,132.32 h1.52
  text "59.20mil" at 262.886,132.32 h1.52
  text "4.8" at 279.391,132.32 h1.52
  text "7" at 206.766,129.272 h1.52
  text "Bottom Layer" at 217.178,129.272 h1.52
  text "Copper" at 241.048,129.272 h1.52
  text "1.40mil" at 262.886,129.272 h1.52
  text "8" at 206.766,126.224 h1.52
  text "Bottom Solder" at 217.178,126.224 h1.52
  text "Solder Resist" at 241.048,126.224 h1.52
  text "0.40mil" at 262.886,126.224 h1.52
  text "3.5" at 279.391,126.224 h1.52
  text "9" at 206.766,123.176 h1.52
  text "Bottom Overlay" at 217.178,123.176 h1.52
  text ".Layer_Name" at -27.792,-42.075 h1.52
M13 Component Bodies Top:
  text ".Layer_Name" at -27.792,-42.075 h1.52
M14 Component Bodies Bottom:
  text ".Layer_Name" at -27.792,-42.075 h1.52
M15 Courtyards Top:
  text ".Layer_Name" at -27.792,-42.075 h1.52
M16 Courtyards Bottom:
  text ".Layer_Name" at -27.792,-42.075 h1.52
Drill Drawing:
  circle w0.254: c93.79,68.302 r0.702
  lines w0.254: 93.088,64.443 94.492,64.443 94.492,65.846 93.088,65.846 93.088,64.443 ; 93.088,71.109 93.439,71.109 93.439,70.758 94.141,70.758 94.141,71.109 94.492,71.109 94.492,71.811 94.141,71.811 94.141,72.162 93.439,72.162 93.439,71.811 93.088,71.811 93.088,71.109 ; 93.088,75.319 94.492,75.319 93.79,73.916 93.088,75.319 ; 93.088,77.424 93.439,77.424 93.79,77.074 94.141,77.424 94.492,77.424 94.141,77.775 94.492,78.126 94.141,78.126 93.79,78.477 93.439,78.126 93.088,78.126 93.439,77.775 93.088,77.424
  lines w0.305: 91.816,63.495 173.896,63.495 ; 91.816,79.284 173.896,79.284 ; 100.398,60.338 100.398,82.442 ; 108.831,60.338 108.831,82.442 ; 124.999,60.338 124.999,82.442 ; 131.582,60.338 131.582,82.442 ; 141.111,60.338 141.111,82.442 ; 159.509,60.338 159.509,82.442 ; 91.816,60.338 173.896,60.338 173.896,82.442 91.816,82.442 91.816,60.338
  text "Symbol" at 93.711,80.231 h1.83
  text "Quantity" at 101.345,80.231 h1.83
  text "Finished Hole Size" at 109.778,80.231 h1.83
  text "Plated" at 125.947,80.231 h1.83
  text "Hole Type" at 132.529,80.231 h1.83
  text "Drill Layer Pair" at 142.058,80.231 h1.83
  text "Hole Tolerance" at 160.456,80.231 h1.83
  text "23" at 101.345,77.074 h1.52
  text "8.00mil (0.203mm)" at 109.778,77.074 h1.52
  text "PTH" at 125.947,77.074 h1.52
  text "Round" at 132.529,77.074 h1.52
  text "Top Layer - Bottom Layer" at 142.058,77.074 h1.52
  text "28" at 101.345,73.916 h1.52
  text "15.75mil (0.400mm)" at 109.778,73.916 h1.52
  text "PTH" at 125.947,73.916 h1.52
  text "Round" at 132.529,73.916 h1.52
  text "Top Layer - Bottom Layer" at 142.058,73.916 h1.52
  text "209" at 101.345,70.758 h1.52
  text "16.00mil (0.406mm)" at 109.778,70.758 h1.52
  text "PTH" at 125.947,70.758 h1.52
  text "Round" at 132.529,70.758 h1.52
  text "Top Layer - Bottom Layer" at 142.058,70.758 h1.52
  text "2" at 101.345,67.6 h1.52
  text "55.12mil (1.400mm)" at 109.778,67.6 h1.52
  text "PTH" at 125.947,67.6 h1.52
  text "Round" at 132.529,67.6 h1.52
  text "Top Layer - Bottom Layer" at 142.058,67.6 h1.52
  text "8" at 101.345,64.443 h1.52
  text "23.62mil (0.600mm)" at 109.778,64.443 h1.52
  text "PTH" at 125.947,64.443 h1.52
  text "Slot" at 132.529,64.443 h1.52
  text "Top Layer - Bottom Layer" at 142.058,64.443 h1.52
  text "270 Total" at 101.345,61.285 h1.52
  text "Slot definitions :" at 93.711,59.075 h1.52
  text "Routed Path Length" at 105.159,59.075 h1.52
  text "= Calculated from tool start centre position to tool end centre position." at 118.868,59.075 h1.52
  text "Hole Length" at 105.159,57.811 h1.52
  text "= Routed Path Length + Tool Size = Slot length as defined in the PCB layout" at 113.793,57.811 h1.52
  text ".Layer_Name" at -27.792,-42.075 h1.52
M17 Embedded Cavity:
  text ".Layer_Name" at -27.792,-42.075 h1.52
M18 Embedded Assembly:
  text ".Layer_Name" at -27.792,-42.075 h1.52
M19 Embedded Keepout:
  text ".Layer_Name" at -27.792,-42.075 h1.52

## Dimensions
0.021,0 to 0.021,35 on M2 Board Dimensions
-42.448,-30.429 to -17.048,-30.429 on M2 Board Dimensions
50.021,0 to 0.021,0 on M2 Board Dimensions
